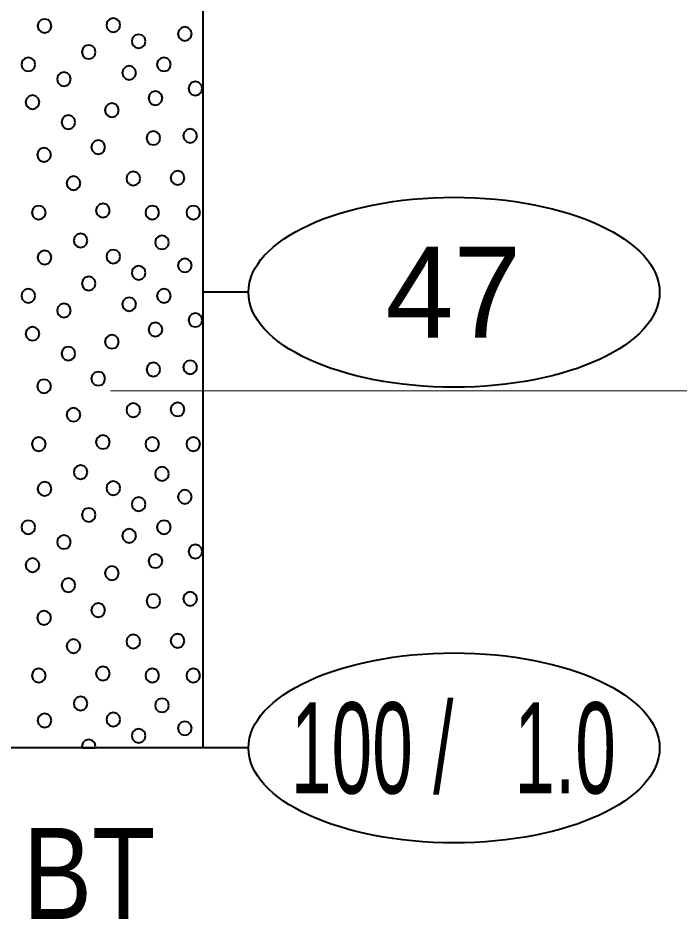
# Model space of a CAD drawing. Extents: x -582 to 653, y -817 to -3.
# Drawn here: x -25 to -17.73, y -559.93 to -550.04 of the extents above; entities that cross this region are included whole.
import ezdxf
from ezdxf.enums import TextEntityAlignment as Align

# ---------------------------------------------------------------- set-up
doc = ezdxf.new("R2010")
doc.units = 0
doc.header["$LTSCALE"] = 0.4
doc.layers.add('27', color=7, linetype='Continuous', lineweight=40)
doc.layers.add('7', color=7, linetype='Continuous', lineweight=13)

msp = doc.modelspace()

# ---------------------------------------------------------------- linework, layer by layer
at = {"layer": '27'}
for p, q in [((-22.4714, -553.0528), (-22.9714, -553.0528)), ((-22.4714, -558.0528), (-22.9714, -558.0528))]:
    msp.add_line(p, q, dxfattribs=at)
for points in [[(-25.4713, -549.7528), (-22.9713, -549.7528), (-22.9713, -558.0528), (-25.4713, -558.0528)], [(-24.6345, -550.1307), (-24.6447, -550.0926), (-24.6726, -550.0647), (-24.7107, -550.0545), (-24.7488, -550.0647), (-24.7767, -550.0926), (-24.7869, -550.1307), (-24.7767, -550.1688), (-24.7488, -550.1967), (-24.7107, -550.2069), (-24.6726, -550.1967), (-24.6447, -550.1688)], [(-23.8794, -550.1217), (-23.8896, -550.0836), (-23.9175, -550.0557), (-23.9556, -550.0455), (-23.9937, -550.0557), (-24.0216, -550.0836), (-24.0318, -550.1217), (-24.0216, -550.1598), (-23.9937, -550.1877), (-23.9556, -550.1979), (-23.9175, -550.1877), (-23.8896, -550.1598)], [(-23.0939, -550.2176), (-23.1041, -550.1795), (-23.132, -550.1516), (-23.1701, -550.1414), (-23.2082, -550.1516), (-23.2361, -550.1795), (-23.2463, -550.2176), (-23.2361, -550.2557), (-23.2082, -550.2836), (-23.1701, -550.2938), (-23.132, -550.2836), (-23.1041, -550.2557)], [(-23.6012, -550.299), (-23.6114, -550.2609), (-23.6393, -550.233), (-23.6774, -550.2228), (-23.7155, -550.233), (-23.7434, -550.2609), (-23.7536, -550.299), (-23.7434, -550.3371), (-23.7155, -550.365), (-23.6774, -550.3752), (-23.6393, -550.365), (-23.6114, -550.3371)], [(-24.1495, -550.4165), (-24.1597, -550.3784), (-24.1876, -550.3505), (-24.2257, -550.3403), (-24.2638, -550.3505), (-24.2917, -550.3784), (-24.3019, -550.4165), (-24.2917, -550.4546), (-24.2638, -550.4825), (-24.2257, -550.4927), (-24.1876, -550.4825), (-24.1597, -550.4546)], [(-24.8127, -550.552), (-24.8229, -550.5139), (-24.8508, -550.486), (-24.8889, -550.4758), (-24.927, -550.486), (-24.9549, -550.5139), (-24.9651, -550.552), (-24.9549, -550.5901), (-24.927, -550.618), (-24.8889, -550.6282), (-24.8508, -550.618), (-24.8229, -550.5901)], [(-23.324, -550.552), (-23.3342, -550.5139), (-23.3621, -550.486), (-23.4002, -550.4758), (-23.4383, -550.486), (-23.4662, -550.5139), (-23.4764, -550.552), (-23.4662, -550.5901), (-23.4383, -550.618), (-23.4002, -550.6282), (-23.3621, -550.618), (-23.3342, -550.5901)], [(-24.4211, -550.7134), (-24.4314, -550.6753), (-24.4592, -550.6474), (-24.4973, -550.6372), (-24.5354, -550.6474), (-24.5633, -550.6753), (-24.5735, -550.7134), (-24.5633, -550.7515), (-24.5354, -550.7794), (-24.4973, -550.7896), (-24.4592, -550.7794), (-24.4314, -550.7515)], [(-23.7054, -550.6448), (-23.7156, -550.6067), (-23.7435, -550.5788), (-23.7816, -550.5686), (-23.8197, -550.5788), (-23.8476, -550.6067), (-23.8578, -550.6448), (-23.8476, -550.6829), (-23.8197, -550.7108), (-23.7816, -550.721), (-23.7435, -550.7108), (-23.7156, -550.6829)], [(-22.9783, -550.8177), (-22.9885, -550.7796), (-23.0164, -550.7517), (-23.0545, -550.7415), (-23.0926, -550.7517), (-23.1204, -550.7796), (-23.1307, -550.8177), (-23.1204, -550.8558), (-23.0926, -550.8837), (-23.0545, -550.8939), (-23.0164, -550.8837), (-22.9885, -550.8558)], [(-23.4168, -550.9219), (-23.4271, -550.8838), (-23.4549, -550.8559), (-23.493, -550.8457), (-23.5311, -550.8559), (-23.559, -550.8838), (-23.5692, -550.9219), (-23.559, -550.96), (-23.5311, -550.9879), (-23.493, -550.9981), (-23.4549, -550.9879), (-23.4271, -550.96)], [(-24.7669, -550.9677), (-24.7771, -550.9296), (-24.805, -550.9017), (-24.8431, -550.8915), (-24.8812, -550.9017), (-24.9091, -550.9296), (-24.9193, -550.9677), (-24.9091, -551.0058), (-24.8812, -551.0337), (-24.8431, -551.0439), (-24.805, -551.0337), (-24.7771, -551.0058)], [(-23.8948, -551.0554), (-23.905, -551.0173), (-23.9329, -550.9894), (-23.971, -550.9792), (-24.0091, -550.9894), (-24.037, -551.0173), (-24.0472, -551.0554), (-24.037, -551.0935), (-24.0091, -551.1214), (-23.971, -551.1316), (-23.9329, -551.1214), (-23.905, -551.0935)], [(-24.3728, -551.1863), (-24.383, -551.1482), (-24.4109, -551.1203), (-24.449, -551.1101), (-24.4871, -551.1203), (-24.515, -551.1482), (-24.5252, -551.1863), (-24.515, -551.2244), (-24.4871, -551.2523), (-24.449, -551.2625), (-24.4109, -551.2523), (-24.383, -551.2244)], [(-23.4397, -551.3605), (-23.4499, -551.3224), (-23.4778, -551.2945), (-23.5159, -551.2843), (-23.554, -551.2945), (-23.5819, -551.3224), (-23.5921, -551.3605), (-23.5819, -551.3986), (-23.554, -551.4265), (-23.5159, -551.4367), (-23.4778, -551.4265), (-23.4499, -551.3986)], [(-23.0355, -551.3363), (-23.0457, -551.2982), (-23.0736, -551.2704), (-23.1117, -551.2601), (-23.1498, -551.2704), (-23.1777, -551.2982), (-23.1879, -551.3363), (-23.1777, -551.3744), (-23.1498, -551.4023), (-23.1117, -551.4125), (-23.0736, -551.4023), (-23.0457, -551.3744)], [(-24.0449, -551.4609), (-24.0551, -551.4228), (-24.083, -551.3949), (-24.1211, -551.3847), (-24.1592, -551.3949), (-24.187, -551.4228), (-24.1973, -551.4609), (-24.187, -551.499), (-24.1592, -551.5269), (-24.1211, -551.5371), (-24.083, -551.5269), (-24.0551, -551.499)], [(-24.6398, -551.5448), (-24.65, -551.5067), (-24.6779, -551.4788), (-24.716, -551.4686), (-24.7541, -551.4788), (-24.782, -551.5067), (-24.7922, -551.5448), (-24.782, -551.5829), (-24.7541, -551.6108), (-24.716, -551.621), (-24.6779, -551.6108), (-24.65, -551.5829)], [(-23.6597, -551.8054), (-23.6699, -551.7673), (-23.6978, -551.7394), (-23.7359, -551.7292), (-23.774, -551.7394), (-23.8018, -551.7673), (-23.8121, -551.8054), (-23.8018, -551.8435), (-23.774, -551.8714), (-23.7359, -551.8816), (-23.6978, -551.8714), (-23.6699, -551.8435)], [(-23.174, -551.7978), (-23.1842, -551.7597), (-23.2121, -551.7318), (-23.2502, -551.7216), (-23.2883, -551.7318), (-23.3162, -551.7597), (-23.3264, -551.7978), (-23.3162, -551.8359), (-23.2883, -551.8638), (-23.2502, -551.874), (-23.2121, -551.8638), (-23.1842, -551.8359)], [(-24.3169, -551.8563), (-24.3271, -551.8182), (-24.355, -551.7903), (-24.3931, -551.7801), (-24.4312, -551.7903), (-24.4591, -551.8182), (-24.4693, -551.8563), (-24.4591, -551.8944), (-24.4312, -551.9223), (-24.3931, -551.9325), (-24.355, -551.9223), (-24.3271, -551.8944)], [(-24.6983, -552.1792), (-24.7085, -552.1411), (-24.7364, -552.1132), (-24.7745, -552.103), (-24.8126, -552.1132), (-24.8405, -552.1411), (-24.8507, -552.1792), (-24.8405, -552.2173), (-24.8126, -552.2452), (-24.7745, -552.2554), (-24.7364, -552.2452), (-24.7085, -552.2173)], [(-23.994, -552.1563), (-24.0042, -552.1182), (-24.0321, -552.0903), (-24.0702, -552.0801), (-24.1083, -552.0903), (-24.1362, -552.1182), (-24.1464, -552.1563), (-24.1362, -552.1944), (-24.1083, -552.2223), (-24.0702, -552.2325), (-24.0321, -552.2223), (-24.0042, -552.1944)], [(-23.4512, -552.1792), (-23.4614, -552.1411), (-23.4893, -552.1132), (-23.5274, -552.103), (-23.5655, -552.1132), (-23.5934, -552.1411), (-23.6036, -552.1792), (-23.5934, -552.2173), (-23.5655, -552.2452), (-23.5274, -552.2554), (-23.4893, -552.2452), (-23.4614, -552.2173)], [(-23.0011, -552.1792), (-23.0113, -552.1411), (-23.0392, -552.1132), (-23.0773, -552.103), (-23.1154, -552.1132), (-23.1433, -552.1411), (-23.1535, -552.1792), (-23.1433, -552.2173), (-23.1154, -552.2452), (-23.0773, -552.2554), (-23.0392, -552.2452), (-23.0113, -552.2173)], [(-24.2384, -552.4859), (-24.2487, -552.4478), (-24.2765, -552.4199), (-24.3146, -552.4097), (-24.3527, -552.4199), (-24.3806, -552.4478), (-24.3908, -552.4859), (-24.3806, -552.524), (-24.3527, -552.5519), (-24.3146, -552.5621), (-24.2765, -552.5519), (-24.2487, -552.524)], [(-23.3448, -552.5055), (-23.355, -552.4674), (-23.3829, -552.4395), (-23.421, -552.4293), (-23.4591, -552.4395), (-23.487, -552.4674), (-23.4972, -552.5055), (-23.487, -552.5436), (-23.4591, -552.5715), (-23.421, -552.5817), (-23.3829, -552.5715), (-23.355, -552.5436)], [(-24.6345, -552.6707), (-24.6447, -552.6326), (-24.6726, -552.6047), (-24.7107, -552.5945), (-24.7488, -552.6047), (-24.7767, -552.6326), (-24.7869, -552.6707), (-24.7767, -552.7088), (-24.7488, -552.7367), (-24.7107, -552.7469), (-24.6726, -552.7367), (-24.6447, -552.7088)], [(-23.8794, -552.6617), (-23.8896, -552.6236), (-23.9175, -552.5957), (-23.9556, -552.5855), (-23.9937, -552.5957), (-24.0216, -552.6236), (-24.0318, -552.6617), (-24.0216, -552.6998), (-23.9937, -552.7277), (-23.9556, -552.7379), (-23.9175, -552.7277), (-23.8896, -552.6998)], [(-23.0939, -552.7576), (-23.1041, -552.7195), (-23.132, -552.6916), (-23.1701, -552.6814), (-23.2082, -552.6916), (-23.2361, -552.7195), (-23.2463, -552.7576), (-23.2361, -552.7957), (-23.2082, -552.8236), (-23.1701, -552.8338), (-23.132, -552.8236), (-23.1041, -552.7957)], [(-23.6012, -552.839), (-23.6114, -552.8009), (-23.6393, -552.773), (-23.6774, -552.7628), (-23.7155, -552.773), (-23.7434, -552.8009), (-23.7536, -552.839), (-23.7434, -552.8771), (-23.7155, -552.905), (-23.6774, -552.9152), (-23.6393, -552.905), (-23.6114, -552.8771)], [(-24.1495, -552.9565), (-24.1597, -552.9184), (-24.1876, -552.8905), (-24.2257, -552.8803), (-24.2638, -552.8905), (-24.2917, -552.9184), (-24.3019, -552.9565), (-24.2917, -552.9946), (-24.2638, -553.0225), (-24.2257, -553.0327), (-24.1876, -553.0225), (-24.1597, -552.9946)], [(-24.8127, -553.092), (-24.8229, -553.0539), (-24.8508, -553.026), (-24.8889, -553.0158), (-24.927, -553.026), (-24.9549, -553.0539), (-24.9651, -553.092), (-24.9549, -553.1301), (-24.927, -553.158), (-24.8889, -553.1682), (-24.8508, -553.158), (-24.8229, -553.1301)], [(-23.324, -553.092), (-23.3342, -553.0539), (-23.3621, -553.026), (-23.4002, -553.0158), (-23.4383, -553.026), (-23.4662, -553.0539), (-23.4764, -553.092), (-23.4662, -553.1301), (-23.4383, -553.158), (-23.4002, -553.1682), (-23.3621, -553.158), (-23.3342, -553.1301)], [(-23.7054, -553.1848), (-23.7156, -553.1467), (-23.7435, -553.1188), (-23.7816, -553.1086), (-23.8197, -553.1188), (-23.8476, -553.1467), (-23.8578, -553.1848), (-23.8476, -553.2229), (-23.8197, -553.2508), (-23.7816, -553.261), (-23.7435, -553.2508), (-23.7156, -553.2229)], [(-24.4211, -553.2534), (-24.4314, -553.2153), (-24.4592, -553.1874), (-24.4973, -553.1772), (-24.5354, -553.1874), (-24.5633, -553.2153), (-24.5735, -553.2534), (-24.5633, -553.2915), (-24.5354, -553.3194), (-24.4973, -553.3296), (-24.4592, -553.3194), (-24.4314, -553.2915)], [(-22.9783, -553.3577), (-22.9885, -553.3196), (-23.0164, -553.2917), (-23.0545, -553.2815), (-23.0926, -553.2917), (-23.1204, -553.3196), (-23.1307, -553.3577), (-23.1204, -553.3958), (-23.0926, -553.4237), (-23.0545, -553.4339), (-23.0164, -553.4237), (-22.9885, -553.3958)], [(-23.4168, -553.4619), (-23.4271, -553.4238), (-23.4549, -553.3959), (-23.493, -553.3857), (-23.5311, -553.3959), (-23.559, -553.4238), (-23.5692, -553.4619), (-23.559, -553.5), (-23.5311, -553.5279), (-23.493, -553.5381), (-23.4549, -553.5279), (-23.4271, -553.5)], [(-24.7669, -553.5077), (-24.7771, -553.4696), (-24.805, -553.4417), (-24.8431, -553.4315), (-24.8812, -553.4417), (-24.9091, -553.4696), (-24.9193, -553.5077), (-24.9091, -553.5458), (-24.8812, -553.5737), (-24.8431, -553.5839), (-24.805, -553.5737), (-24.7771, -553.5458)], [(-23.8948, -553.5954), (-23.905, -553.5573), (-23.9329, -553.5294), (-23.971, -553.5192), (-24.0091, -553.5294), (-24.037, -553.5573), (-24.0472, -553.5954), (-24.037, -553.6335), (-24.0091, -553.6614), (-23.971, -553.6716), (-23.9329, -553.6614), (-23.905, -553.6335)], [(-24.3728, -553.7263), (-24.383, -553.6882), (-24.4109, -553.6603), (-24.449, -553.6501), (-24.4871, -553.6603), (-24.515, -553.6882), (-24.5252, -553.7263), (-24.515, -553.7644), (-24.4871, -553.7923), (-24.449, -553.8025), (-24.4109, -553.7923), (-24.383, -553.7644)], [(-23.0355, -553.8763), (-23.0457, -553.8382), (-23.0736, -553.8104), (-23.1117, -553.8001), (-23.1498, -553.8104), (-23.1777, -553.8382), (-23.1879, -553.8763), (-23.1777, -553.9144), (-23.1498, -553.9423), (-23.1117, -553.9525), (-23.0736, -553.9423), (-23.0457, -553.9144)], [(-23.4397, -553.9005), (-23.4499, -553.8624), (-23.4778, -553.8345), (-23.5159, -553.8243), (-23.554, -553.8345), (-23.5819, -553.8624), (-23.5921, -553.9005), (-23.5819, -553.9386), (-23.554, -553.9665), (-23.5159, -553.9767), (-23.4778, -553.9665), (-23.4499, -553.9386)], [(-24.6398, -554.0848), (-24.65, -554.0467), (-24.6779, -554.0188), (-24.716, -554.0086), (-24.7541, -554.0188), (-24.782, -554.0467), (-24.7922, -554.0848), (-24.782, -554.1229), (-24.7541, -554.1508), (-24.716, -554.161), (-24.6779, -554.1508), (-24.65, -554.1229)], [(-24.0449, -554.0009), (-24.0551, -553.9628), (-24.083, -553.9349), (-24.1211, -553.9247), (-24.1592, -553.9349), (-24.187, -553.9628), (-24.1973, -554.0009), (-24.187, -554.039), (-24.1592, -554.0669), (-24.1211, -554.0771), (-24.083, -554.0669), (-24.0551, -554.039)], [(-23.6597, -554.3454), (-23.6699, -554.3073), (-23.6978, -554.2794), (-23.7359, -554.2692), (-23.774, -554.2794), (-23.8018, -554.3073), (-23.8121, -554.3454), (-23.8018, -554.3835), (-23.774, -554.4114), (-23.7359, -554.4216), (-23.6978, -554.4114), (-23.6699, -554.3835)], [(-23.174, -554.3378), (-23.1842, -554.2997), (-23.2121, -554.2718), (-23.2502, -554.2616), (-23.2883, -554.2718), (-23.3162, -554.2997), (-23.3264, -554.3378), (-23.3162, -554.3759), (-23.2883, -554.4038), (-23.2502, -554.414), (-23.2121, -554.4038), (-23.1842, -554.3759)], [(-24.3169, -554.3963), (-24.3271, -554.3582), (-24.355, -554.3303), (-24.3931, -554.3201), (-24.4312, -554.3303), (-24.4591, -554.3582), (-24.4693, -554.3963), (-24.4591, -554.4344), (-24.4312, -554.4623), (-24.3931, -554.4725), (-24.355, -554.4623), (-24.3271, -554.4344)], [(-24.6983, -554.7192), (-24.7085, -554.6811), (-24.7364, -554.6532), (-24.7745, -554.643), (-24.8126, -554.6532), (-24.8405, -554.6811), (-24.8507, -554.7192), (-24.8405, -554.7573), (-24.8126, -554.7852), (-24.7745, -554.7954), (-24.7364, -554.7852), (-24.7085, -554.7573)], [(-23.994, -554.6963), (-24.0042, -554.6582), (-24.0321, -554.6303), (-24.0702, -554.6201), (-24.1083, -554.6303), (-24.1362, -554.6582), (-24.1464, -554.6963), (-24.1362, -554.7344), (-24.1083, -554.7623), (-24.0702, -554.7725), (-24.0321, -554.7623), (-24.0042, -554.7344)], [(-23.4512, -554.7192), (-23.4614, -554.6811), (-23.4893, -554.6532), (-23.5274, -554.643), (-23.5655, -554.6532), (-23.5934, -554.6811), (-23.6036, -554.7192), (-23.5934, -554.7573), (-23.5655, -554.7852), (-23.5274, -554.7954), (-23.4893, -554.7852), (-23.4614, -554.7573)], [(-23.0011, -554.7192), (-23.0113, -554.6811), (-23.0392, -554.6532), (-23.0773, -554.643), (-23.1154, -554.6532), (-23.1433, -554.6811), (-23.1535, -554.7192), (-23.1433, -554.7573), (-23.1154, -554.7852), (-23.0773, -554.7954), (-23.0392, -554.7852), (-23.0113, -554.7573)], [(-24.2384, -555.0259), (-24.2487, -554.9878), (-24.2765, -554.9599), (-24.3146, -554.9497), (-24.3527, -554.9599), (-24.3806, -554.9878), (-24.3908, -555.0259), (-24.3806, -555.064), (-24.3527, -555.0919), (-24.3146, -555.1021), (-24.2765, -555.0919), (-24.2487, -555.064)], [(-23.3448, -555.0455), (-23.355, -555.0074), (-23.3829, -554.9795), (-23.421, -554.9693), (-23.4591, -554.9795), (-23.487, -555.0074), (-23.4972, -555.0455), (-23.487, -555.0836), (-23.4591, -555.1115), (-23.421, -555.1217), (-23.3829, -555.1115), (-23.355, -555.0836)], [(-24.6345, -555.2107), (-24.6447, -555.1726), (-24.6726, -555.1447), (-24.7107, -555.1345), (-24.7488, -555.1447), (-24.7767, -555.1726), (-24.7869, -555.2107), (-24.7767, -555.2488), (-24.7488, -555.2767), (-24.7107, -555.2869), (-24.6726, -555.2767), (-24.6447, -555.2488)], [(-23.8794, -555.2017), (-23.8896, -555.1636), (-23.9175, -555.1357), (-23.9556, -555.1255), (-23.9937, -555.1357), (-24.0216, -555.1636), (-24.0318, -555.2017), (-24.0216, -555.2398), (-23.9937, -555.2677), (-23.9556, -555.2779), (-23.9175, -555.2677), (-23.8896, -555.2398)], [(-23.0939, -555.2976), (-23.1041, -555.2595), (-23.132, -555.2316), (-23.1701, -555.2214), (-23.2082, -555.2316), (-23.2361, -555.2595), (-23.2463, -555.2976), (-23.2361, -555.3357), (-23.2082, -555.3636), (-23.1701, -555.3738), (-23.132, -555.3636), (-23.1041, -555.3357)], [(-23.6012, -555.379), (-23.6114, -555.3409), (-23.6393, -555.313), (-23.6774, -555.3028), (-23.7155, -555.313), (-23.7434, -555.3409), (-23.7536, -555.379), (-23.7434, -555.4171), (-23.7155, -555.445), (-23.6774, -555.4552), (-23.6393, -555.445), (-23.6114, -555.4171)], [(-24.1495, -555.4965), (-24.1597, -555.4584), (-24.1876, -555.4305), (-24.2257, -555.4203), (-24.2638, -555.4305), (-24.2917, -555.4584), (-24.3019, -555.4965), (-24.2917, -555.5346), (-24.2638, -555.5625), (-24.2257, -555.5727), (-24.1876, -555.5625), (-24.1597, -555.5346)], [(-24.8127, -555.632), (-24.8229, -555.5939), (-24.8508, -555.566), (-24.8889, -555.5558), (-24.927, -555.566), (-24.9549, -555.5939), (-24.9651, -555.632), (-24.9549, -555.6701), (-24.927, -555.698), (-24.8889, -555.7082), (-24.8508, -555.698), (-24.8229, -555.6701)], [(-23.324, -555.632), (-23.3342, -555.5939), (-23.3621, -555.566), (-23.4002, -555.5558), (-23.4383, -555.566), (-23.4662, -555.5939), (-23.4764, -555.632), (-23.4662, -555.6701), (-23.4383, -555.698), (-23.4002, -555.7082), (-23.3621, -555.698), (-23.3342, -555.6701)], [(-23.7054, -555.7248), (-23.7156, -555.6867), (-23.7435, -555.6588), (-23.7816, -555.6486), (-23.8197, -555.6588), (-23.8476, -555.6867), (-23.8578, -555.7248), (-23.8476, -555.7629), (-23.8197, -555.7908), (-23.7816, -555.801), (-23.7435, -555.7908), (-23.7156, -555.7629)], [(-24.4211, -555.7934), (-24.4314, -555.7553), (-24.4592, -555.7274), (-24.4973, -555.7172), (-24.5354, -555.7274), (-24.5633, -555.7553), (-24.5735, -555.7934), (-24.5633, -555.8315), (-24.5354, -555.8594), (-24.4973, -555.8696), (-24.4592, -555.8594), (-24.4314, -555.8315)], [(-22.9783, -555.8977), (-22.9885, -555.8596), (-23.0164, -555.8317), (-23.0545, -555.8215), (-23.0926, -555.8317), (-23.1204, -555.8596), (-23.1307, -555.8977), (-23.1204, -555.9358), (-23.0926, -555.9637), (-23.0545, -555.9739), (-23.0164, -555.9637), (-22.9885, -555.9358)], [(-24.7669, -556.0477), (-24.7771, -556.0096), (-24.805, -555.9817), (-24.8431, -555.9715), (-24.8812, -555.9817), (-24.9091, -556.0096), (-24.9193, -556.0477), (-24.9091, -556.0858), (-24.8812, -556.1137), (-24.8431, -556.1239), (-24.805, -556.1137), (-24.7771, -556.0858)], [(-23.4168, -556.0019), (-23.4271, -555.9638), (-23.4549, -555.9359), (-23.493, -555.9257), (-23.5311, -555.9359), (-23.559, -555.9638), (-23.5692, -556.0019), (-23.559, -556.04), (-23.5311, -556.0679), (-23.493, -556.0781), (-23.4549, -556.0679), (-23.4271, -556.04)], [(-23.8948, -556.1354), (-23.905, -556.0973), (-23.9329, -556.0694), (-23.971, -556.0592), (-24.0091, -556.0694), (-24.037, -556.0973), (-24.0472, -556.1354), (-24.037, -556.1735), (-24.0091, -556.2014), (-23.971, -556.2116), (-23.9329, -556.2014), (-23.905, -556.1735)], [(-24.3728, -556.2663), (-24.383, -556.2282), (-24.4109, -556.2003), (-24.449, -556.1901), (-24.4871, -556.2003), (-24.515, -556.2282), (-24.5252, -556.2663), (-24.515, -556.3044), (-24.4871, -556.3323), (-24.449, -556.3425), (-24.4109, -556.3323), (-24.383, -556.3044)], [(-23.4397, -556.4405), (-23.4499, -556.4024), (-23.4778, -556.3745), (-23.5159, -556.3643), (-23.554, -556.3745), (-23.5819, -556.4024), (-23.5921, -556.4405), (-23.5819, -556.4786), (-23.554, -556.5065), (-23.5159, -556.5167), (-23.4778, -556.5065), (-23.4499, -556.4786)], [(-23.0355, -556.4163), (-23.0457, -556.3782), (-23.0736, -556.3504), (-23.1117, -556.3401), (-23.1498, -556.3504), (-23.1777, -556.3782), (-23.1879, -556.4163), (-23.1777, -556.4544), (-23.1498, -556.4823), (-23.1117, -556.4925), (-23.0736, -556.4823), (-23.0457, -556.4544)], [(-24.0449, -556.5409), (-24.0551, -556.5028), (-24.083, -556.4749), (-24.1211, -556.4647), (-24.1592, -556.4749), (-24.187, -556.5028), (-24.1973, -556.5409), (-24.187, -556.579), (-24.1592, -556.6069), (-24.1211, -556.6171), (-24.083, -556.6069), (-24.0551, -556.579)], [(-24.6398, -556.6248), (-24.65, -556.5867), (-24.6779, -556.5588), (-24.716, -556.5486), (-24.7541, -556.5588), (-24.782, -556.5867), (-24.7922, -556.6248), (-24.782, -556.6629), (-24.7541, -556.6908), (-24.716, -556.701), (-24.6779, -556.6908), (-24.65, -556.6629)], [(-24.3169, -556.9363), (-24.3271, -556.8982), (-24.355, -556.8703), (-24.3931, -556.8601), (-24.4312, -556.8703), (-24.4591, -556.8982), (-24.4693, -556.9363), (-24.4591, -556.9744), (-24.4312, -557.0023), (-24.3931, -557.0125), (-24.355, -557.0023), (-24.3271, -556.9744)], [(-23.6597, -556.8854), (-23.6699, -556.8473), (-23.6978, -556.8194), (-23.7359, -556.8092), (-23.774, -556.8194), (-23.8018, -556.8473), (-23.8121, -556.8854), (-23.8018, -556.9235), (-23.774, -556.9514), (-23.7359, -556.9616), (-23.6978, -556.9514), (-23.6699, -556.9235)], [(-23.174, -556.8778), (-23.1842, -556.8397), (-23.2121, -556.8118), (-23.2502, -556.8016), (-23.2883, -556.8118), (-23.3162, -556.8397), (-23.3264, -556.8778), (-23.3162, -556.9159), (-23.2883, -556.9438), (-23.2502, -556.954), (-23.2121, -556.9438), (-23.1842, -556.9159)], [(-23.994, -557.2363), (-24.0042, -557.1982), (-24.0321, -557.1703), (-24.0702, -557.1601), (-24.1083, -557.1703), (-24.1362, -557.1982), (-24.1464, -557.2363), (-24.1362, -557.2744), (-24.1083, -557.3023), (-24.0702, -557.3125), (-24.0321, -557.3023), (-24.0042, -557.2744)], [(-24.6983, -557.2592), (-24.7085, -557.2211), (-24.7364, -557.1932), (-24.7745, -557.183), (-24.8126, -557.1932), (-24.8405, -557.2211), (-24.8507, -557.2592), (-24.8405, -557.2973), (-24.8126, -557.3252), (-24.7745, -557.3354), (-24.7364, -557.3252), (-24.7085, -557.2973)], [(-23.4512, -557.2592), (-23.4614, -557.2211), (-23.4893, -557.1932), (-23.5274, -557.183), (-23.5655, -557.1932), (-23.5934, -557.2211), (-23.6036, -557.2592), (-23.5934, -557.2973), (-23.5655, -557.3252), (-23.5274, -557.3354), (-23.4893, -557.3252), (-23.4614, -557.2973)], [(-23.0011, -557.2592), (-23.0113, -557.2211), (-23.0392, -557.1932), (-23.0773, -557.183), (-23.1154, -557.1932), (-23.1433, -557.2211), (-23.1535, -557.2592), (-23.1433, -557.2973), (-23.1154, -557.3252), (-23.0773, -557.3354), (-23.0392, -557.3252), (-23.0113, -557.2973)], [(-24.2384, -557.5659), (-24.2487, -557.5278), (-24.2765, -557.4999), (-24.3146, -557.4897), (-24.3527, -557.4999), (-24.3806, -557.5278), (-24.3908, -557.5659), (-24.3806, -557.604), (-24.3527, -557.6319), (-24.3146, -557.6421), (-24.2765, -557.6319), (-24.2487, -557.604)], [(-23.3448, -557.5855), (-23.355, -557.5474), (-23.3829, -557.5195), (-23.421, -557.5093), (-23.4591, -557.5195), (-23.487, -557.5474), (-23.4972, -557.5855), (-23.487, -557.6236), (-23.4591, -557.6515), (-23.421, -557.6617), (-23.3829, -557.6515), (-23.355, -557.6236)], [(-24.6345, -557.7507), (-24.6447, -557.7126), (-24.6726, -557.6847), (-24.7107, -557.6745), (-24.7488, -557.6847), (-24.7767, -557.7126), (-24.7869, -557.7507), (-24.7767, -557.7888), (-24.7488, -557.8167), (-24.7107, -557.8269), (-24.6726, -557.8167), (-24.6447, -557.7888)], [(-23.8794, -557.7417), (-23.8896, -557.7036), (-23.9175, -557.6757), (-23.9556, -557.6655), (-23.9937, -557.6757), (-24.0216, -557.7036), (-24.0318, -557.7417), (-24.0216, -557.7798), (-23.9937, -557.8077), (-23.9556, -557.8179), (-23.9175, -557.8077), (-23.8896, -557.7798)], [(-23.0939, -557.8376), (-23.1041, -557.7995), (-23.132, -557.7716), (-23.1701, -557.7614), (-23.2082, -557.7716), (-23.2361, -557.7995), (-23.2463, -557.8376), (-23.2361, -557.8757), (-23.2082, -557.9036), (-23.1701, -557.9138), (-23.132, -557.9036), (-23.1041, -557.8757)], [(-23.6012, -557.919), (-23.6114, -557.8809), (-23.6393, -557.853), (-23.6774, -557.8428), (-23.7155, -557.853), (-23.7434, -557.8809), (-23.7536, -557.919), (-23.7434, -557.9571), (-23.7155, -557.985), (-23.6774, -557.9952), (-23.6393, -557.985), (-23.6114, -557.9571)], [(-24.1495, -558.0365), (-24.1597, -557.9984), (-24.1876, -557.9705), (-24.2257, -557.9603), (-24.2638, -557.9705), (-24.2917, -557.9984), (-24.3019, -558.0365), (-24.2975, -558.0528), (-24.1539, -558.0528)]]:
    msp.add_lwpolyline(points, close=True, dxfattribs=at)
for centre in [(-20.214, -553.0528), (-20.214, -558.0528)]:
    msp.add_ellipse(centre, major_axis=(2.2574, 0), ratio=0.461538, dxfattribs=at)
at = {"layer": '7'}
for p, q in [((-23.9857, -554.1328), (27.5287, -554.1328)), ((-22.9713, -554.1328), (28.379, -554.1328))]:
    msp.add_line(p, q, dxfattribs=at)

# ---------------------------------------------------------------- texts
at = {"layer": '27'}
msp.add_text('47', height=1, dxfattribs=at).set_placement((-20.2213, -553.5528), align=Align.CENTER)
for s, width, p in [('100 /   1.0', 0.6, (-20.2213, -558.5528)), ('BT', 0.85, (-24.2213, -559.9297))]:
    msp.add_text(s, height=1, dxfattribs=dict(at, width=width)).set_placement(p, align=Align.CENTER)

doc.saveas('drawing.dxf')
